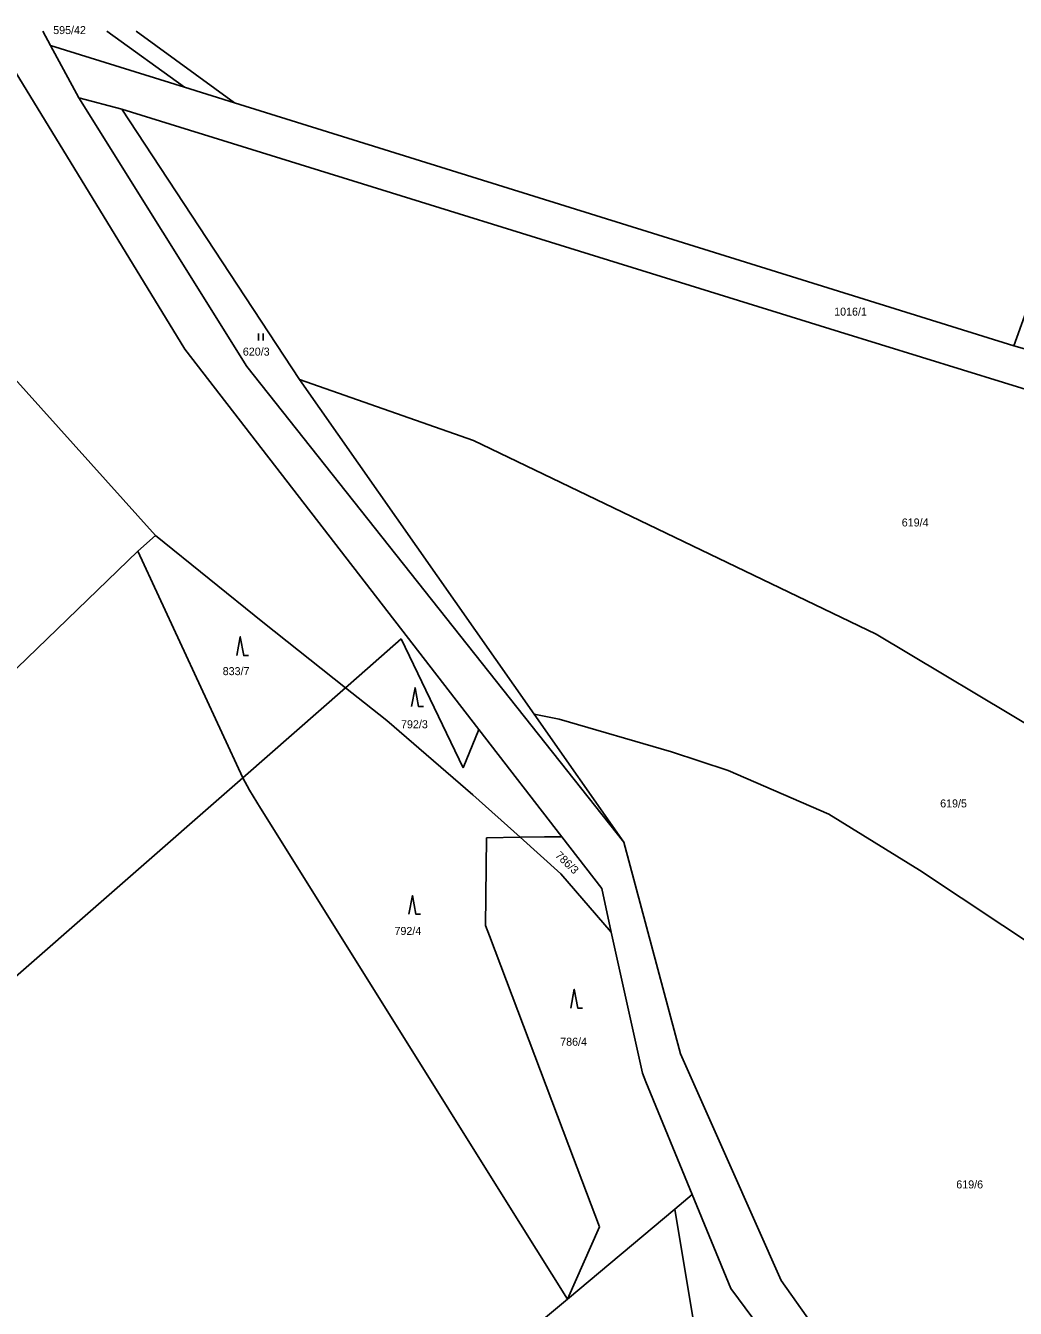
# Model space of a CAD drawing. Extents: x -801907 to -800293, y -1017000 to -1015684.
# Drawn here: x -801017.4 to -800807.1, y -1015956.5 to -1015684 of the extents above; entities that cross this region are included whole.
import ezdxf

# ---------------------------------------------------------------- set-up
doc = ezdxf.new("R2010")
doc.units = 0
for name, color, linetype in [('Default', 7, 'Continuous'), ('KN_HRANICE', 7, 'Continuous'), ('KN_KULTURY', 7, 'Continuous'), ('KN_PARCELY', 7, 'Continuous')]:
    doc.layers.add(name, color=color, linetype=linetype)

# ---------------------------------------------------------------- blocks, each defined once
blk = doc.blocks.new('306')
at = {"layer": 'Default'}
for p, q in [((-0.5, 1.5), (-0.5, 0)), ((0.5, 0), (0.5, 1.5))]:
    blk.add_line(p, q, dxfattribs=at)
blk = doc.blocks.new('308')
at = {"layer": 'Default'}
blk.add_lwpolyline([(-0.75, 0), (0, 4), (0.75, 0), (1.75, 0)], dxfattribs=at)

msp = doc.modelspace()

# ---------------------------------------------------------------- linework, layer by layer
at = {"layer": 'KN_HRANICE'}
for p, q in [((-800983.5, -1015752.75), (-801024.84, -1015685.21)), ((-801013.68, -1015685.21), (-801012.05, -1015688.24)), ((-801000.1, -1015685.21), (-800983.62, -1015697.1)), ((-800972.99, -1015700.41), (-800993.89, -1015685.21)), ((-800983.62, -1015697.1), (-801012.05, -1015688.24)), ((-801012.05, -1015688.24), (-801006.07, -1015699.36)), ((-801006.07, -1015699.36), (-800996.93, -1015701.79)), ((-801006.07, -1015699.36), (-800970.33, -1015756.48)), ((-800972.99, -1015700.41), (-800983.62, -1015697.1)), ((-800996.93, -1015701.79), (-800959.17, -1015759.19)), ((-800996.93, -1015701.79), (-800844.45, -1015749.07)), ((-800807.39, -1015752.04), (-800972.99, -1015700.41)), ((-800801.84, -1015736.69), (-800807.39, -1015752.04)), ((-800844.45, -1015749.07), (-800789.06, -1015766.22)), ((-800921.06, -1015833.54), (-800983.5, -1015752.75)), ((-800807.39, -1015752.04), (-800745.55, -1015769.62)), ((-800970.33, -1015756.48), (-800890.22, -1015857.51)), ((-801021.02, -1015757.57), (-800989.74, -1015792.38)), ((-800959.17, -1015759.19), (-800922.2, -1015772.19)), ((-800959.17, -1015759.19), (-800909.31, -1015830.28)), ((-800922.2, -1015772.19), (-800836.63, -1015813.33)), ((-800993.49, -1015795.71), (-800989.74, -1015792.38)), ((-800989.74, -1015792.38), (-800966.99, -1015810.73)), ((-800993.49, -1015795.71), (-801064.33, -1015863.91)), ((-800993.49, -1015795.71), (-800971.23, -1015843.82)), ((-800966.99, -1015810.73), (-800949.4, -1015824.7)), ((-800836.63, -1015813.33), (-800721.7, -1015882.03)), ((-800937.53, -1015814.3), (-800946.48, -1015822.14)), ((-800937.53, -1015814.3), (-800924.37, -1015841.72)), ((-800946.48, -1015822.14), (-800949.4, -1015824.7)), ((-800949.4, -1015824.7), (-800971.23, -1015843.82)), ((-800949.4, -1015824.7), (-800945.34, -1015827.93)), ((-800945.34, -1015827.93), (-800940.63, -1015831.67)), ((-800903.98, -1015831.4), (-800909.31, -1015830.28)), ((-800909.31, -1015830.28), (-800890.22, -1015857.51)), ((-800940.63, -1015831.67), (-800922.31, -1015847.45)), ((-800880.13, -1015838.34), (-800903.98, -1015831.4)), ((-800924.37, -1015841.72), (-800921.06, -1015833.54)), ((-800903.44, -1015856.34), (-800921.06, -1015833.54)), ((-800868.11, -1015842.25), (-800880.13, -1015838.34)), ((-800971.23, -1015843.82), (-801082.92, -1015941.56)), ((-800971.23, -1015843.82), (-800969.81, -1015846.48)), ((-800846.73, -1015851.52), (-800868.11, -1015842.25)), ((-800969.81, -1015846.48), (-800967.45, -1015850.26)), ((-800922.31, -1015847.45), (-800912.26, -1015856.47)), ((-800967.45, -1015850.26), (-800939.34, -1015895.22)), ((-800827.41, -1015863.42), (-800846.73, -1015851.52)), ((-800919.41, -1015856.57), (-800919.62, -1015875.22)), ((-800919.41, -1015856.57), (-800912.26, -1015856.47)), ((-800912.26, -1015856.47), (-800907.11, -1015856.39)), ((-800912.26, -1015856.47), (-800903.63, -1015864.21)), ((-800907.11, -1015856.39), (-800903.44, -1015856.34)), ((-800894.96, -1015867.31), (-800903.44, -1015856.34)), ((-800890.22, -1015857.51), (-800878.19, -1015902.48)), ((-800903.63, -1015864.21), (-800892.91, -1015876.64)), ((-800769.79, -1015901.81), (-800827.41, -1015863.42)), ((-800892.91, -1015876.64), (-800894.96, -1015867.31)), ((-800919.62, -1015875.22), (-800918.8, -1015877.38)), ((-800886.32, -1015906.55), (-800892.91, -1015876.64)), ((-800918.8, -1015877.38), (-800901.91, -1015922.02)), ((-800939.34, -1015895.22), (-800915.51, -1015933.33)), ((-800878.19, -1015902.48), (-800867.74, -1015926.02)), ((-800885.55, -1015908.42), (-800886.32, -1015906.55)), ((-800875.73, -1015932.38), (-800885.55, -1015908.42)), ((-800901.91, -1015922.02), (-800895.41, -1015939.21)), ((-800867.74, -1015926.02), (-800856.81, -1015950.64)), ((-800915.51, -1015933.33), (-800902.23, -1015954.58)), ((-800879.42, -1015935.47), (-800875.73, -1015932.38)), ((-800867.55, -1015952.33), (-800875.73, -1015932.38)), ((-800902.23, -1015954.58), (-800879.42, -1015935.47)), ((-800871.54, -1015982.97), (-800879.42, -1015935.47)), ((-800895.41, -1015939.21), (-800902.23, -1015954.58)), ((-800836.58, -1015993.67), (-800867.55, -1015952.33)), ((-800856.81, -1015950.64), (-800842.4, -1015970.92)), ((-800906.9, -1015958.49), (-800902.23, -1015954.58))]:
    msp.add_line(p, q, dxfattribs=at)

# ---------------------------------------------------------------- block references
at = {"layer": 'KN_KULTURY'}
for name, p in [('306', (-800967.35, -1015750.92)), ('308', (-800971.75, -1015817.87)), ('308', (-800934.6, -1015828.71)), ('308', (-800935.18, -1015872.83)), ('308', (-800900.78, -1015892.76))]:
    msp.add_blockref(name, p, dxfattribs=at)

# ---------------------------------------------------------------- texts
at = {"layer": 'KN_PARCELY'}
for s, p in [('595/42', (-801011.5, -1015685.83)), ('1016/1', (-800845.56, -1015745.64)), ('620/3', (-800971.2, -1015754.14)), ('619/4', (-800831.2, -1015790.43)), ('833/7', (-800975.48, -1015822.02)), ('792/3', (-800937.59, -1015833.3)), ('619/5', (-800823.04, -1015850.12)), ('792/4', (-800938.98, -1015877.21)), ('786/4', (-800903.77, -1015900.75)), ('619/6', (-800819.61, -1015931.06))]:
    msp.add_text(s, height=1.7, dxfattribs=at).set_placement(p)
msp.add_text('786/3', height=1.7, rotation=316.044, dxfattribs=at).set_placement((-800904.94, -1015860.47))

doc.saveas('drawing.dxf')
